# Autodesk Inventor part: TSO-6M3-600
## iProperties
Author: Ron Crain
Shininess: 25.0
Angle Display Precision: 2
Document Length Units: 11269
Document Angle Units: 11284
Document Time Units: 11279
Document Mass Units: 11290
Document Length Units Precision: 2
Document Angle Units Precision: 2
Compacted: True
PropertySet Name: _Private Model Information
Created: 2002-07
Part Number: TSO-6M3-600
Material: Steel, High Strength Low Alloy
Description: STANDOFF, THREADED, THK WALL SELF CLINCH, M3x0.5 X 6 mm
Vendor: PENN ENG. & MFG
Document SubType Name: Modeling
Designer: Ron Crain
Control State: 0
Master: False
Checked Out: False
PropertySet Name: Design Tracking Control
Density: 7.84
Volumn: 0.17245559573138858
Area: 3.4800931280430336
PropertySet Name: Model Information
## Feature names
1. Extrusion1
2. Extrusion2
3. Revolution1
4. Revolution2
5. Rectangular Pattern1
6. Hole1
7. Chamfer3
8. Chamfer4
